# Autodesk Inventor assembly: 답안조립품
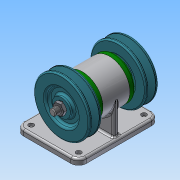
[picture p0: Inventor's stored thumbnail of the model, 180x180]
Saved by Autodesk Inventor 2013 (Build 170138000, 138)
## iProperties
Created: 2019-09
Part Number: 답안조립품
Document SubType Name: Assembly
Designer: Administrator
Author: Administrator
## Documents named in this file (10)
- C:\Users\Administrator\Desktop\490904V1029\답안조립품.iam
- C:\Users\Administrator\Desktop\490904V1029\본체.ipt
- C:\Users\Administrator\Desktop\490904V1029\V-벨트풀리.ipt
- C:\Users\Administrator\Desktop\490904V1029\너트 M10x1.ipt
- C:\Users\Administrator\Desktop\490904V1029\베어링 6004.ipt
- C:\Users\Administrator\Desktop\490904V1029\볼트 M4.ipt
- C:\Users\Administrator\Desktop\490904V1029\오일 실 17 30 5.ipt
- C:\Users\Administrator\Desktop\490904V1029\축.ipt
- C:\Users\Administrator\Desktop\490904V1029\커버.ipt
- C:\Users\Administrator\Desktop\490904V1029\키 5 x 5 x 12.ipt
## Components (2 placed, 1 different names)
1. V-벨트풀리:1
2. V-벨트풀리:2
